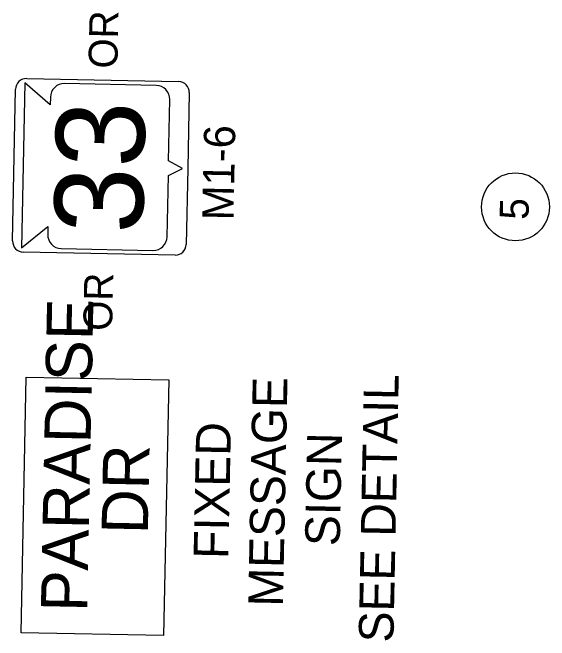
# Model space of a CAD drawing. Extents: x 345549 to 379569, y 127949 to 230467.
# Drawn here: x 357741 to 360523, y 223607 to 226863 of the extents above; entities that cross this region are included whole.
import ezdxf

# ---------------------------------------------------------------- set-up
doc = ezdxf.new("R2010")
doc.units = 0
doc.layers.add('CA-TEXT', color=7, linetype='Continuous')
doc.layers.add('P_SGN_Cell', color=7, linetype='Continuous')

msp = doc.modelspace()

# ---------------------------------------------------------------- linework, layer by layer
at = {"layer": 'CA-TEXT'}
msp.add_circle((360347.1, 225854.8), 175.9, dxfattribs=at)
at = {"layer": 'P_SGN_Cell'}
for p, q in [((357804.9, 226498.9), (357787.6, 225642.8)), ((357937, 226383.7), (357804.9, 226498.9)), ((357814.7, 226520.5), (358602, 226504.7)), ((358486, 226485.1), (358011.1, 226494.7)), ((357741.5, 225678.1), (357757.3, 226465.4)), ((358657.1, 226447.3), (358649.2, 226053.7)), ((357937.8, 226424.3), (357937, 226383.7)), ((358550, 226093.2), (358556.4, 226411.8)), ((358621.1, 226054.2), (358550, 226093.2)), ((358548.5, 226018.2), (358621.1, 226054.2)), ((358649.2, 226053.7), (358641.3, 225660)), ((358542.1, 225699.5), (358548.5, 226018.2)), ((357787.6, 225642.8), (357924.3, 225752.6)), ((357924.3, 225752.6), (357923.4, 225711.9)), ((358583.9, 225604.9), (357796.6, 225620.7)), ((357993.9, 225638.6), (358468.7, 225629.1))]:
    msp.add_line(p, q, dxfattribs=at)
msp.add_lwpolyline([(357785.9, 223646.6), (357812.6, 224972), (358551, 224957.2), (358524.3, 223631.7)], close=True, dxfattribs=at)
for centre, radius, start, end in [((357813.6, 226464.3), 56.2, 88.8462, 178.8462), ((358009.6, 226422.9), 71.9, 88.8462, 178.8462), ((358600.9, 226448.5), 56.2, 358.8462, 88.8462), ((358484.5, 226413.3), 71.9, 358.8462, 88.8462), ((357995.3, 225710.5), 71.9, 178.8462, 268.8462), ((357797.7, 225677), 56.2, 178.8462, 268.8462), ((358470.2, 225700.9), 71.9, 268.8462, 358.8462), ((358585, 225661.1), 56.2, 268.8462, 358.8462)]:
    msp.add_arc(centre, radius, start, end, dxfattribs=at)

# ---------------------------------------------------------------- texts
at = {"layer": 'CA-TEXT'}
for s, p in [('OR', (358284.5, 226571.1)), ('5', (360414.8, 225787.3)), ('OR', (358257.2, 225211))]:
    msp.add_text(s, height=150, rotation=88.8468, dxfattribs=at).set_placement(p)
at = {"layer": 'P_SGN_Cell'}
for s, height, p in [('33', 460, (358415.8, 225713.9)), ('M1-6', 162, (358885.9, 225783.8)), ('PARADISE', 240, (358127.9, 223753.4)), ('MESSAGE', 180, (359142.1, 223780.6)), ('SEE DETAIL', 180, (359714.5, 223594.8)), ('FIXED', 180, (358859.1, 224028)), ('SIGN', 180, (359436.5, 224094.4)), ('DR', 240, (358442.2, 224156.5))]:
    msp.add_text(s, height=height, rotation=88.8462, dxfattribs=at).set_placement(p)

doc.saveas('drawing.dxf')
